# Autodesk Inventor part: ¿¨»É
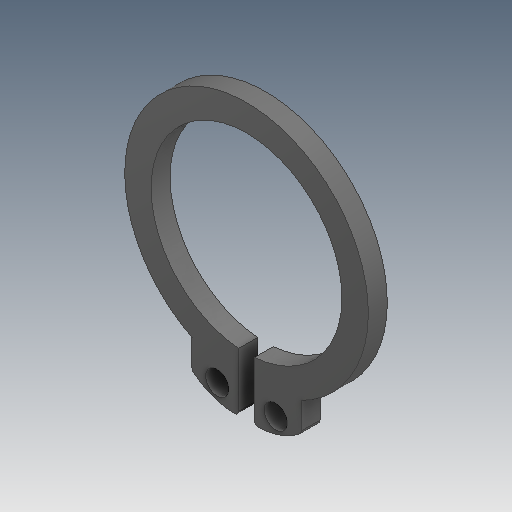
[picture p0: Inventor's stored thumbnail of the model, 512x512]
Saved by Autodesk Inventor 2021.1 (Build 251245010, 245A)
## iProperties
Created: 2021-05
Part Number: ¿¨»É
Material: Ogólny
Document SubType Name: Modeling
Designer: user
Density: 1 g/cm^3
Appearance: Domyślna
Author: user
Revision Number: ÈÎºÎ
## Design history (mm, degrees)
feature "ÊäÈë1"
node "Bryła1"
